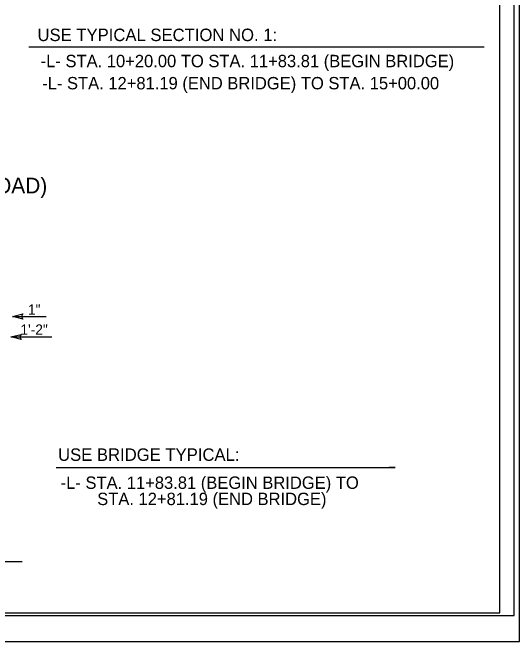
# Model space of a CAD drawing. Extents: x 573980 to 574178, y -53449 to -53334.
# Drawn here: x 574110 to 574156.2, y -53449 to -53391.7 of the extents above; entities that cross this region are included whole.
import ezdxf

# ---------------------------------------------------------------- set-up
doc = ezdxf.new("R2010")
doc.units = 0
for name, color, linetype in [('Old_Level_1', 7, 'Continuous'), ('Old_Level_11', 7, 'Continuous'), ('Old_Level_60', 7, 'Continuous'), ('Prop Dimension Text', 7, 'Continuous'), ('Sheet Plot Border Inside CELL', 7, 'Continuous'), ('Sheet Plot Border Outside CELL', 7, 'Continuous'), ('Sheet Typical CELL', 7, 'Continuous'), ('Typical Terminator CELL', 7, 'Continuous'), ('Typical Text General CELL', 7, 'Continuous')]:
    doc.layers.add(name, color=color, linetype=linetype)

# ---------------------------------------------------------------- blocks, each defined once
blk = doc.blocks.new('TERMINATOR')
at = {"layer": 'Typical Terminator CELL'}
blk.add_lwpolyline([(-0.469, 0.081), (0, 0), (-0.471, -0.083), (-0.411, 0)], close=True, dxfattribs=at)

msp = doc.modelspace()

# ---------------------------------------------------------------- linework, layer by layer
at = {"layer": 'Old_Level_1'}
msp.add_line((574067.039, -53441.751), (574110.919, -53441.751), dxfattribs=at)
at = {"layer": 'Old_Level_11'}
for p, q in [((574111.52, -53394.857), (574137.874, -53394.857)), ((574137.874, -53394.857), (574152.995, -53394.857)), ((574114.017, -53433.192), (574144.908, -53433.192)), ((574144.908, -53433.192), (574144.355, -53433.192))]:
    msp.add_line(p, q, dxfattribs=at)
at = {"layer": 'Prop Dimension Text'}
for p, q in [((574110.032, -53419.434), (574113.102, -53419.434)), ((574109.882, -53421.299), (574113.622, -53421.299))]:
    msp.add_line(p, q, dxfattribs=at)
at = {"layer": 'Sheet Plot Border Inside CELL'}
msp.add_lwpolyline([(574155.747, -53336.331), (573981.441, -53336.331), (573981.441, -53446.688), (574155.747, -53446.688)], close=True, dxfattribs=at)
at = {"layer": 'Sheet Plot Border Outside CELL'}
msp.add_lwpolyline([(574156.218, -53333.982), (573980.081, -53333.982), (573980.081, -53449.036), (574156.218, -53449.036)], close=True, dxfattribs=at)
at = {"layer": 'Sheet Typical CELL'}
msp.add_lwpolyline([(574154.44, -53336.597), (573997.548, -53336.597), (573997.548, -53446.421), (574154.44, -53446.421)], close=True, dxfattribs=at)

# ---------------------------------------------------------------- block references
at = {"layer": 'Old_Level_11', "xscale": 1.9883351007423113, "yscale": 2.8538812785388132, "rotation": 179.9999999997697}
for p in [(574110.032, -53419.434), (574109.882, -53421.299)]:
    msp.add_blockref('TERMINATOR', p, dxfattribs=at)

# ---------------------------------------------------------------- texts
at = {"layer": 'Old_Level_11'}
for s, p in [('USE TYPICAL SECTION NO. 1:', (574112.302, -53394.341)), ('USE BRIDGE TYPICAL: ', (574114.178, -53432.586))]:
    msp.add_text(s, height=1.13476, dxfattribs=at).set_placement(p)
at = {"layer": 'Old_Level_60'}
for s, p in [('-L- STA. 10+20.00 TO STA. 11+83.81 (BEGIN BRIDGE)', (574112.592, -53396.719)), ('-L- STA. 12+81.19 (END BRIDGE) TO STA. 15+00.00', (574112.731, -53398.737)), ('-L- STA. 11+83.81 (BEGIN BRIDGE) TO', (574114.412, -53435.137)), ('STA. 12+81.19 (END BRIDGE)', (574117.744, -53436.614))]:
    msp.add_text(s, height=1.12661, dxfattribs=at).set_placement(p)
at = {"layer": 'Prop Dimension Text'}
for s, p in [('1"', (574111.432, -53419.27)), ('1\'-2"', (574110.747, -53421.094))]:
    msp.add_text(s, height=0.9375, rotation=360, dxfattribs=at).set_placement(p)
at = {"layer": 'Typical Text General CELL'}
msp.add_text('(BLACKSNAKE ROAD)', height=1.42332, dxfattribs=at).set_placement((574093.203, -53408.212))

doc.saveas('drawing.dxf')
